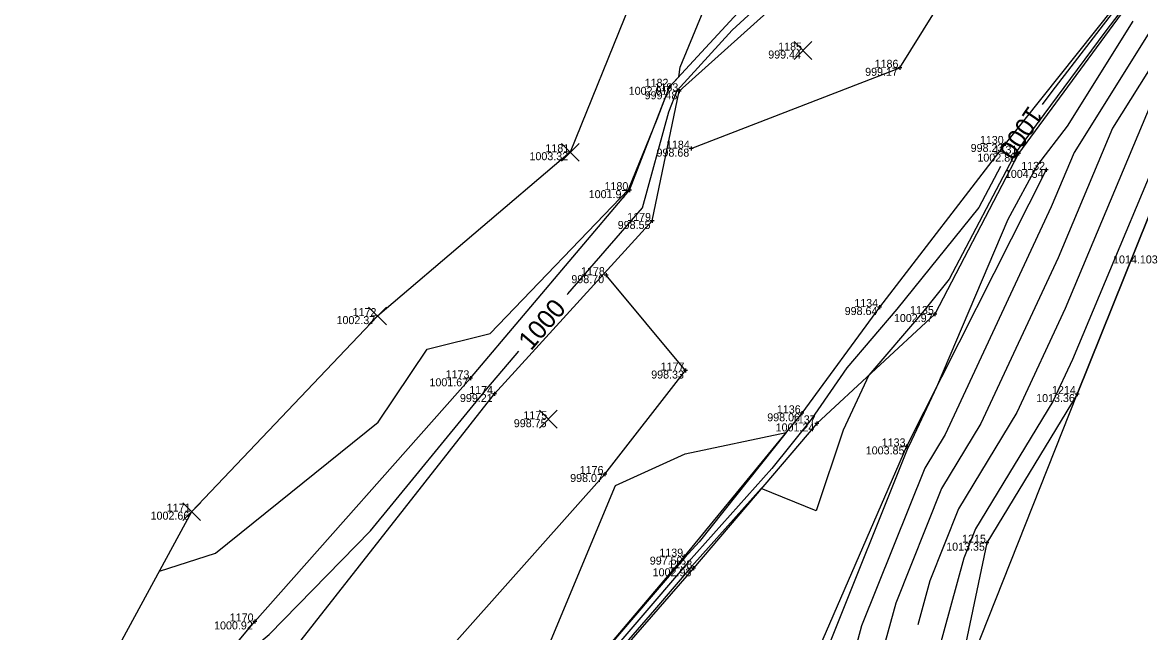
# Model space of a CAD drawing. Extents: x 2354693 to 2355622, y 637071 to 710080.
# Drawn here: x 2355086 to 2355253.6, y 708901.8 to 708993.3 of the extents above; entities that cross this region are included whole.
import ezdxf

# ---------------------------------------------------------------- set-up
doc = ezdxf.new("R2010")
doc.units = 0
for name, color, linetype in [('Default', 7, 'Continuous'), ('DT_X_Contour_Major', 7, 'Continuous'), ('DT_X_Contour_Minor', 7, 'Continuous'), ('HY_X_Water_Edge', 7, 'Continuous'), ('SV_X_Random_Point', 7, 'Continuous'), ('SV_X_Shot_Marker', 7, 'Continuous'), ('SV_X_Text_Elevation', 7, 'Continuous'), ('SV_X_Text_Name', 7, 'Continuous'), ('SV_X_Toe_of_Slope', 7, 'Continuous'), ('SV_X_Top_of_Bank', 7, 'Continuous')]:
    doc.layers.add(name, color=color, linetype=linetype)

msp = doc.modelspace()

# ---------------------------------------------------------------- linework, layer by layer
at = {"layer": 'Default'}
msp.add_lwpolyline([(2355203.89, 709062.28), (2355168.12, 708973.83), (2355139.21, 708949.25), (2355111.34, 708919.92), (2355085.96, 708873.19), (2355092.11, 708843.77), (2355125.13, 708818.02), (2355154.71, 708803.16), (2355181.45, 708791.76), (2355202.79, 708842.86), (2355225.29, 708890), (2355244.12, 708937.56), (2355263.76, 708986.4), (2355330.91, 709003.61)], dxfattribs=at)
msp.add_lwpolyline([(2355203.89, 709062.28), (2355168.12, 708973.83), (2355139.21, 708949.25), (2355111.34, 708919.92), (2355085.96, 708873.19), (2355092.11, 708843.77), (2355125.13, 708818.02), (2355154.71, 708803.16), (2355181.45, 708791.76), (2355202.79, 708842.86), (2355225.29, 708890), (2355244.12, 708937.56), (2355263.76, 708986.4), (2355330.91, 709003.61)], dxfattribs=at)
at = {"layer": 'DT_X_Contour_Major'}
for points in [[(2355274.9, 709071.46), (2355274.78, 709054.92), (2355274.64, 709045.69), (2355270.39, 709036.96), (2355249.89, 708995.32), (2355240.33, 708982.95), (2355238.86, 708980.97)], [(2355274.9, 709071.46), (2355274.78, 709054.92), (2355274.64, 709045.69), (2355270.39, 709036.96), (2355249.89, 708995.32), (2355240.33, 708982.95), (2355238.86, 708980.97)], [(2355167.69, 708952.51), (2355167.75, 708952.58), (2355178.96, 708965.48), (2355182.91, 708979.9), (2355184.16, 708983.1), (2355192.4, 708992.11), (2355221.92, 709019.26), (2355224.3, 709021.9), (2355229.14, 709028.96)], [(2355167.69, 708952.51), (2355167.75, 708952.58), (2355178.96, 708965.48), (2355182.91, 708979.9), (2355184.16, 708983.1), (2355192.4, 708992.11), (2355221.92, 709019.26), (2355224.3, 709021.9), (2355229.14, 709028.96)], [(2355262.48, 708993.24), (2355260.02, 708988.76), (2355255.18, 708981.03), (2355242.34, 708950.38), (2355235.07, 708934.78), (2355226.34, 708920.36), (2355222.02, 708909.57), (2355220.21, 708902.96)], [(2355262.48, 708993.24), (2355260.02, 708988.76), (2355255.18, 708981.03), (2355242.34, 708950.38), (2355235.07, 708934.78), (2355226.34, 708920.36), (2355222.02, 708909.57), (2355220.21, 708902.96)], [(2355232.61, 708971.71), (2355229.37, 708965.55), (2355217.08, 708950.28), (2355209.56, 708941.48), (2355204.21, 708933.75), (2355198.35, 708926.39), (2355185.83, 708912.39), (2355170.05, 708893.95)], [(2355232.61, 708971.71), (2355229.37, 708965.55), (2355217.08, 708950.28), (2355209.56, 708941.48), (2355204.21, 708933.75), (2355198.35, 708926.39), (2355185.83, 708912.39), (2355170.05, 708893.95)], [(2355091.83, 708884), (2355102.22, 708887.3), (2355103.22, 708882.47), (2355114.9, 708894.74), (2355114.9, 708894.74), (2355122.96, 708901.48), (2355138.18, 708917.03), (2355155.58, 708938.33), (2355160.42, 708943.99)], [(2355091.83, 708884), (2355102.22, 708887.3), (2355103.22, 708882.47), (2355114.9, 708894.74), (2355114.9, 708894.74), (2355122.96, 708901.48), (2355138.18, 708917.03), (2355155.58, 708938.33), (2355160.42, 708943.99)]]:
    msp.add_lwpolyline(points, dxfattribs=at)
at = {"layer": 'DT_X_Contour_Minor'}
for points in [[(2355106.5, 708911.01), (2355114.93, 708913.69), (2355139.33, 708933.32), (2355146.64, 708944.28), (2355156.1, 708946.64), (2355176.84, 708968.25), (2355181.12, 708978.77), (2355183.01, 708983.64), (2355184.37, 708985.13), (2355184.57, 708986.57), (2355207.42, 709041.98), (2355208.28, 709062.3), (2355204.23, 709063.58)], [(2355106.5, 708911.01), (2355114.93, 708913.69), (2355139.33, 708933.32), (2355146.64, 708944.28), (2355156.1, 708946.64), (2355176.84, 708968.25), (2355181.12, 708978.77), (2355183.01, 708983.64), (2355184.37, 708985.13), (2355184.57, 708986.57), (2355207.42, 709041.98), (2355208.28, 709062.3), (2355204.23, 709063.58)], [(2355285.39, 709028.91), (2355262.53, 708987.18), (2355260.94, 708984.64), (2355243.4, 708942.76), (2355240.45, 708936.43), (2355228.87, 708917.33), (2355227.13, 708912.97), (2355221.28, 708891.6), (2355217.16, 708883.36), (2355197.22, 708846.27), (2355192.4, 708838.49), (2355176.54, 708801.86), (2355173.83, 708795)], [(2355285.39, 709028.91), (2355262.53, 708987.18), (2355260.94, 708984.64), (2355243.4, 708942.76), (2355240.45, 708936.43), (2355228.87, 708917.33), (2355227.13, 708912.97), (2355221.28, 708891.6), (2355217.16, 708883.36), (2355197.22, 708846.27), (2355192.4, 708838.49), (2355176.54, 708801.86), (2355173.83, 708795)], [(2355270.62, 709014.28), (2355257.51, 708990.34), (2355249.42, 708977.42), (2355241.28, 708958), (2355229.69, 708933.13), (2355223.8, 708923.4), (2355216.91, 708906.18), (2355213.74, 708894.61), (2355201.89, 708870.88), (2355190.78, 708850.22), (2355180.4, 708833.43), (2355171.35, 708812.54), (2355165.79, 708798.43)], [(2355270.62, 709014.28), (2355257.51, 708990.34), (2355249.42, 708977.42), (2355241.28, 708958), (2355229.69, 708933.13), (2355223.8, 708923.4), (2355216.91, 708906.18), (2355213.74, 708894.61), (2355201.89, 708870.88), (2355190.78, 708850.22), (2355180.4, 708833.43), (2355171.35, 708812.54), (2355165.79, 708798.43)], [(2355263.24, 709006.97), (2355254.99, 708991.91), (2355243.66, 708973.81), (2355240.23, 708965.62), (2355224.31, 708931.48), (2355221.26, 708926.44), (2355211.79, 708902.78), (2355209.96, 708896.11), (2355194.26, 708864.64), (2355187.56, 708852.19), (2355174.4, 708830.91), (2355168.76, 708817.88), (2355161.76, 708800.15)], [(2355263.24, 709006.97), (2355254.99, 708991.91), (2355243.66, 708973.81), (2355240.23, 708965.62), (2355224.31, 708931.48), (2355221.26, 708926.44), (2355211.79, 708902.78), (2355209.96, 708896.11), (2355194.26, 708864.64), (2355187.56, 708852.19), (2355174.4, 708830.91), (2355168.76, 708817.88), (2355161.76, 708800.15)], [(2355250.54, 708994.76), (2355248.29, 708991.85), (2355234.96, 708973.88), (2355224.93, 708954.79), (2355220.91, 708949.79), (2355212.87, 708940.38), (2355209.01, 708932.15), (2355204.99, 708920.04), (2355196.76, 708923.38), (2355186.34, 708911.74), (2355180.74, 708905.19), (2355156.4, 708877.09), (2355154.65, 708875.63), (2355153.75, 708874.12), (2355151.75, 708867.8), (2355141.57, 708850.26), (2355135.2, 708840.27), (2355134.64, 708837.52), (2355135.81, 708829.29), (2355129.21, 708827.4), (2355125.61, 708825.87), (2355121.27, 708821.71), (2355112.53, 708827.85)], [(2355250.54, 708994.76), (2355248.29, 708991.85), (2355234.96, 708973.88), (2355224.93, 708954.79), (2355220.91, 708949.79), (2355212.87, 708940.38), (2355209.01, 708932.15), (2355204.99, 708920.04), (2355196.76, 708923.38), (2355186.34, 708911.74), (2355180.74, 708905.19), (2355156.4, 708877.09), (2355154.65, 708875.63), (2355153.75, 708874.12), (2355151.75, 708867.8), (2355141.57, 708850.26), (2355135.2, 708840.27), (2355134.64, 708837.52), (2355135.81, 708829.29), (2355129.21, 708827.4), (2355125.61, 708825.87), (2355121.27, 708821.71), (2355112.53, 708827.85)], [(2355252.48, 708993.49), (2355242.63, 708977.76), (2355238.16, 708971.94), (2355233.7, 708963.72), (2355223.01, 708938.58), (2355218.93, 708929.83), (2355218.72, 708929.48), (2355206.68, 708899.39), (2355206.19, 708897.61), (2355186.62, 708858.4), (2355184.34, 708854.16), (2355168.4, 708828.38), (2355166.16, 708823.22), (2355157.74, 708801.86)], [(2355252.48, 708993.49), (2355242.63, 708977.76), (2355238.16, 708971.94), (2355233.7, 708963.72), (2355223.01, 708938.58), (2355218.93, 708929.83), (2355218.72, 708929.48), (2355206.68, 708899.39), (2355206.19, 708897.61), (2355186.62, 708858.4), (2355184.34, 708854.16), (2355168.4, 708828.38), (2355166.16, 708823.22), (2355157.74, 708801.86)], [(2355156.25, 708879.08), (2355174.92, 708923.86), (2355185.32, 708928.6), (2355200.49, 708931.8), (2355187.44, 708915.42), (2355185.31, 708913.04), (2355156.25, 708879.08)], [(2355156.25, 708879.08), (2355174.92, 708923.86), (2355185.32, 708928.6), (2355200.49, 708931.8), (2355187.44, 708915.42), (2355185.31, 708913.04), (2355156.25, 708879.08)]]:
    msp.add_lwpolyline(points, dxfattribs=at)
at = {"layer": 'HY_X_Water_Edge'}
for points in [[(2355272.75, 709215.1), (2355272.74, 709215.09), (2355269.55, 709175.73), (2355269.77, 709147.81), (2355269.19, 709105.65), (2355274.67, 709084.44), (2355274.45, 709045.7), (2355249.64, 708995.53), (2355233.3, 708975.07), (2355214.48, 708950.61), (2355202.85, 708934.67), (2355185.21, 708913.18), (2355155.78, 708878.52), (2355144.35, 708868.9), (2355107.99, 708834.31)], [(2355093.48, 708843.59), (2355091.82, 708860.88), (2355101.34, 708874.79), (2355126.1, 708898.55), (2355156.73, 708937.57), (2355180.39, 708963.52), (2355184.45, 708982.97), (2355223.4, 709017.99), (2355237.5, 709039.04), (2355220.47, 709066.41), (2355205.69, 709069.16)]]:
    msp.add_lwpolyline(points, dxfattribs=at)
at = {"layer": 'SV_X_Random_Point'}
for p, q in [((2355201.68, 708987.74), (2355204.35, 708990.41)), ((2355201.68, 708990.41), (2355204.35, 708987.74)), ((2355166.79, 708972.49), (2355169.45, 708975.16)), ((2355166.79, 708975.16), (2355169.45, 708972.49)), ((2355137.87, 708947.92), (2355140.54, 708950.59)), ((2355137.87, 708950.59), (2355140.54, 708947.92)), ((2355163.48, 708932.46), (2355166.14, 708935.13)), ((2355163.48, 708935.13), (2355166.14, 708932.46)), ((2355110, 708918.59), (2355112.67, 708921.26)), ((2355110, 708921.26), (2355112.67, 708918.59))]:
    msp.add_line(p, q, dxfattribs=at)
at = {"layer": 'SV_X_Shot_Marker'}
for p, q in [((2355217.81, 708986.49), (2355217.21, 708986.49)), ((2355217.51, 708986.79), (2355217.51, 708986.19)), ((2355183.3, 708983.64), (2355182.7, 708983.64)), ((2355183, 708983.94), (2355183, 708983.34)), ((2355184.45, 708983.27), (2355184.45, 708982.67)), ((2355184.75, 708982.97), (2355184.15, 708982.97)), ((2355233.6, 708975.07), (2355233, 708975.07)), ((2355233.3, 708975.37), (2355233.3, 708974.77)), ((2355186.54, 708974.37), (2355185.94, 708974.37)), ((2355186.24, 708974.67), (2355186.24, 708974.07)), ((2355235.62, 708973.62), (2355235.02, 708973.62)), ((2355235.32, 708973.92), (2355235.32, 708973.32)), ((2355239.46, 708971.48), (2355239.46, 708970.88)), ((2355239.75, 708971.18), (2355239.16, 708971.18)), ((2355177.32, 708968.14), (2355176.72, 708968.14)), ((2355177.02, 708968.44), (2355177.02, 708967.84)), ((2355180.69, 708963.52), (2355180.09, 708963.52)), ((2355180.39, 708963.82), (2355180.39, 708963.22)), ((2355173.78, 708955.39), (2355173.18, 708955.39)), ((2355173.48, 708955.69), (2355173.48, 708955.09)), ((2355214.78, 708950.61), (2355214.18, 708950.61)), ((2355214.48, 708950.91), (2355214.48, 708950.31)), ((2355223.08, 708949.56), (2355222.48, 708949.56)), ((2355222.78, 708949.86), (2355222.78, 708949.26)), ((2355185.4, 708941.39), (2355185.4, 708940.79)), ((2355153.44, 708939.92), (2355152.84, 708939.92)), ((2355153.14, 708940.22), (2355153.14, 708939.62)), ((2355185.7, 708941.09), (2355185.1, 708941.09)), ((2355156.73, 708937.87), (2355156.73, 708937.27)), ((2355244.12, 708937.86), (2355244.12, 708937.26)), ((2355157.03, 708937.57), (2355156.43, 708937.57)), ((2355244.42, 708937.56), (2355243.82, 708937.56)), ((2355203.15, 708934.67), (2355202.55, 708934.67)), ((2355202.85, 708934.97), (2355202.85, 708934.37)), ((2355205.38, 708933.16), (2355204.78, 708933.16)), ((2355205.08, 708933.46), (2355205.08, 708932.86)), ((2355218.83, 708929.71), (2355218.23, 708929.71)), ((2355218.53, 708930.01), (2355218.53, 708929.41)), ((2355173.58, 708925.57), (2355172.98, 708925.57)), ((2355173.28, 708925.87), (2355173.28, 708925.27)), ((2355230.89, 708915.27), (2355230.29, 708915.27)), ((2355230.59, 708915.57), (2355230.59, 708914.97)), ((2355185.51, 708913.18), (2355184.91, 708913.18)), ((2355185.21, 708913.48), (2355185.21, 708912.88)), ((2355186.88, 708911.43), (2355186.28, 708911.43)), ((2355186.58, 708911.73), (2355186.58, 708911.13)), ((2355121.13, 708903.46), (2355120.53, 708903.46)), ((2355120.83, 708903.76), (2355120.83, 708903.16))]:
    msp.add_line(p, q, dxfattribs=at)
at = {"layer": 'SV_X_Toe_of_Slope'}
for points in [[(2355342.79, 709267.27), (2355319.66, 709264.93), (2355304.72, 709256.21), (2355286.48, 709242.45), (2355272.74, 709215.09), (2355269.55, 709175.73), (2355269.77, 709147.81), (2355269.19, 709105.65), (2355274.67, 709084.44), (2355274.45, 709045.7), (2355249.64, 708995.53), (2355233.3, 708975.07), (2355214.48, 708950.61), (2355202.85, 708934.67), (2355185.21, 708913.18), (2355155.78, 708878.52), (2355144.35, 708868.9), (2355107.99, 708834.31)], [(2355093.48, 708843.59), (2355091.82, 708860.88), (2355101.34, 708874.79), (2355126.1, 708898.55), (2355156.73, 708937.57), (2355180.39, 708963.52), (2355184.45, 708982.97), (2355223.4, 709017.99), (2355237.5, 709039.04), (2355220.47, 709066.41), (2355205.69, 709069.16)], [(2355186.24, 708974.37), (2355217.51, 708986.49), (2355231.45, 709008.93), (2355223.43, 709017.94)], [(2355239.46, 708971.18), (2355218.53, 708929.71), (2355204.83, 708898.16), (2355182.68, 708855.18), (2355164.46, 708826.72), (2355154.71, 708803.16)], [(2355101.32, 708874.78), (2355107.8, 708851.6), (2355136.97, 708884.7), (2355173.28, 708925.57), (2355185.4, 708941.09), (2355173.48, 708955.39)]]:
    msp.add_lwpolyline(points, dxfattribs=at)
at = {"layer": 'SV_X_Top_of_Bank'}
for points in [[(2355273.36, 709199.07), (2355271.07, 709175.55), (2355271.92, 709154.64), (2355272.23, 709141.56), (2355270.63, 709105.68), (2355275.83, 709084.35), (2355276.25, 709045.62), (2355250.74, 708994.59), (2355235.32, 708973.62), (2355222.78, 708949.56), (2355205.08, 708933.16), (2355186.58, 708911.43), (2355156.5, 708876.84), (2355146.53, 708867.02), (2355127.53, 708842.2), (2355110.99, 708831.54)], [(2355092.11, 708843.77), (2355088.4, 708864.8), (2355120.83, 708903.46), (2355153.14, 708939.92), (2355177.02, 708968.14), (2355183, 708983.64), (2355218.52, 709022.16), (2355226.6, 709031.85), (2355225.79, 709044.32), (2355216.32, 709062.32), (2355203.89, 709062.28)], [(2355286.26, 709029.77), (2355263.76, 708986.4), (2355244.12, 708937.56), (2355230.59, 708915.27), (2355225.29, 708890), (2355202.79, 708842.86), (2355181.45, 708791.76)]]:
    msp.add_lwpolyline(points, dxfattribs=at)

# ---------------------------------------------------------------- texts
at = {"layer": 'DT_X_Contour_Major'}
for rotation, p in [(235.9363, (2355236.87, 708980.95)), (235.9363, (2355236.87, 708980.95)), (49.4888, (2355162.22, 708943.95)), (49.4888, (2355162.22, 708943.95))]:
    msp.add_text('1000', height=2.8, rotation=rotation, dxfattribs=at).set_placement(p)
at = {"layer": 'SV_X_Text_Elevation'}
for s, p in [('999.44', (2355197.8, 708987.88)), ('999.17', (2355212.33, 708985.29)), ('1002.01', (2355176.88, 708982.44)), ('999.48', (2355179.27, 708981.77)), ('998.23', (2355228.15, 708973.87)), ('1003.32', (2355162, 708972.63)), ('998.68', (2355181.05, 708973.17)), ('1002.80', (2355229.16, 708972.42)), ('1004.54', (2355233.28, 708969.98)), ('1001.97', (2355170.88, 708966.94)), ('998.55', (2355175.23, 708962.32)), ('1014.103', (2355249.5, 708957.15)), ('998.70', (2355168.28, 708954.19)), ('998.64', (2355209.26, 708949.41)), ('1002.97', (2355216.64, 708948.36)), ('1002.37', (2355133.07, 708948.05)), ('1001.67', (2355147, 708938.72)), ('998.33', (2355180.25, 708939.89)), ('999.21', (2355151.57, 708936.37)), ('1013.36', (2355237.97, 708936.36)), ('998.06', (2355197.65, 708933.47)), ('998.75', (2355159.65, 708932.59)), ('1001.24', (2355198.91, 708931.96)), ('1003.85', (2355212.42, 708928.51)), ('998.07', (2355168.1, 708924.37)), ('1002.66', (2355105.19, 708918.72)), ('1013.35', (2355224.48, 708914.07)), ('997.59', (2355180.04, 708911.98)), ('1002.93', (2355180.47, 708910.23)), ('1000.92', (2355114.71, 708902.26))]:
    msp.add_text(s, height=1.2, dxfattribs=at).set_placement(p)
at = {"layer": 'SV_X_Text_Name'}
for s, p in [('1185', (2355199.29, 708989.08)), ('1186', (2355213.75, 708986.49)), ('1182', (2355179.27, 708983.64)), ('1183', (2355180.74, 708982.97)), ('1181', (2355164.39, 708973.83)), ('1184', (2355182.46, 708974.37)), ('1130', (2355229.53, 708975.07)), ('1131', (2355231.59, 708973.62)), ('1132', (2355235.73, 708971.18)), ('1180', (2355173.25, 708968.14)), ('1179', (2355176.65, 708963.52)), ('1178', (2355169.73, 708955.39)), ('1134', (2355210.7, 708950.61)), ('1172', (2355135.48, 708949.25)), ('1135', (2355219.06, 708949.56)), ('1177', (2355181.66, 708941.09)), ('1173', (2355149.42, 708939.92)), ('1174', (2355152.96, 708937.57)), ('1214', (2355240.34, 708937.56)), ('1175', (2355161.09, 708933.79)), ('1136', (2355199.09, 708934.67)), ('1137', (2355201.34, 708933.16)), ('1133', (2355214.81, 708929.71)), ('1176', (2355169.53, 708925.57)), ('1171', (2355107.61, 708919.92)), ('1215', (2355226.87, 708915.27)), ('1139', (2355181.47, 708913.18)), ('1138', (2355182.83, 708911.43)), ('1170', (2355117.06, 708903.46))]:
    msp.add_text(s, height=1.2, dxfattribs=at).set_placement(p)

doc.saveas('drawing.dxf')
